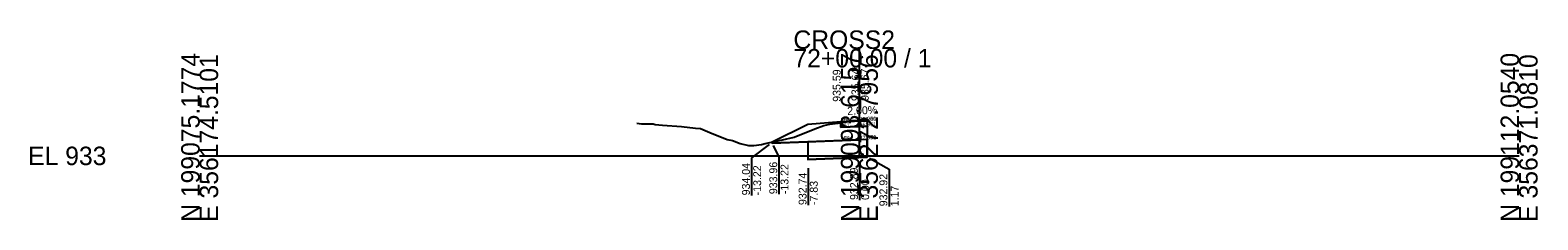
# Model space of a CAD drawing. Extents: x -26 to 203, y -10 to 14021.
# Drawn here: x -25.7 to 202.8, y 12990.3 to 13019.1 of the extents above; entities that cross this region are included whole.
import ezdxf

# ---------------------------------------------------------------- set-up
doc = ezdxf.new("R2010")
doc.units = 0
for name, color, linetype in [('Default', 7, 'Continuous'), ('P_E_XS_Ground', 7, 'Continuous'), ('P_XS', 7, 'Continuous'), ('P_XS_Bold', 7, 'Continuous'), ('P_XS_EAR_CommonGrnd', 7, 'Continuous'), ('P_XS_Lane', 7, 'Continuous'), ('P_XS_Rock', 7, 'Continuous')]:
    doc.layers.add(name, color=color, linetype=linetype)

msp = doc.modelspace()

# ---------------------------------------------------------------- linework, layer by layer
at = {"layer": 'Default'}
for p, q in [((100, 13000), (100, 13016.21)), ((0, 13000), (100, 13000)), ((100, 13000), (200, 13000))]:
    msp.add_line(p, q, dxfattribs=at)
at = {"layer": 'P_E_XS_Ground'}
for p, q in [((66.26, 13004.98), (66.99, 13004.88)), ((66.99, 13004.88), (68.73, 13004.84)), ((68.73, 13004.84), (69.04, 13004.77)), ((69.04, 13004.77), (70.15, 13004.66)), ((70.15, 13004.66), (73.05, 13004.44)), ((73.05, 13004.44), (75.17, 13004.22)), ((75.17, 13004.22), (75.92, 13004.16)), ((75.92, 13004.16), (77.32, 13003.56)), ((77.32, 13003.56), (79.94, 13002.5)), ((90.11, 13002.84), (93.24, 13004.1)), ((93.24, 13004.1), (94.61, 13004.59)), ((94.61, 13004.59), (95.5, 13004.82)), ((95.5, 13004.82), (97.28, 13005.05)), ((97.28, 13005.05), (98.42, 13005.22)), ((98.42, 13005.22), (98.9, 13005.29)), ((98.9, 13005.29), (100, 13005.32)), ((100, 13005.32), (100.66, 13005.34)), ((100.66, 13005.34), (101.18, 13005.4)), ((79.94, 13002.5), (80.76, 13002.31)), ((80.76, 13002.31), (81.92, 13001.86)), ((81.92, 13001.86), (83.21, 13001.58)), ((83.21, 13001.58), (83.99, 13001.55)), ((83.99, 13001.55), (85.16, 13001.74)), ((85.16, 13001.74), (85.71, 13001.86)), ((85.71, 13001.86), (88.35, 13002.41)), ((88.35, 13002.41), (90.11, 13002.84))]:
    msp.add_line(p, q, dxfattribs=at)
at = {"layer": 'P_XS'}
for p, q in [((97.17, 13004.34), (97.17, 13005.17)), ((97.17, 13004.34), (100, 13004.45)), ((101.17, 13004.5), (100, 13004.45)), ((101.17, 13005.33), (101.17, 13004.5)), ((101.17, 13004.5), (101.17, 13002.5)), ((86.78, 13001.92), (100, 13002.45)), ((86.78, 13002.08), (86.78, 13001.92)), ((92.17, 13002.14), (92.17, 12999.47)), ((101.17, 13002.5), (100, 13002.45)), ((101.17, 13002.5), (101.17, 12999.83)), ((101.17, 12999.83), (92.17, 12999.47))]:
    msp.add_line(p, q, dxfattribs=at)
at = {"layer": 'P_XS_EAR_CommonGrnd'}
for points in [[(93.24, 13004.1), (94.61, 13004.59), (95.5, 13004.82), (97.17, 13005.03), (97.17, 13005.17), (92.17, 13004.77), (86.78, 13002.08), (88.35, 13002.41), (90.11, 13002.84)], [(101.17, 13002.5), (100, 13002.45), (92.17, 13002.14), (86.78, 13001.92), (86.78, 13002.08), (88.35, 13002.41), (90.11, 13002.84), (93.24, 13004.1), (94.61, 13004.59), (95.5, 13004.82), (97.17, 13005.03), (97.17, 13004.34), (100, 13004.45), (101.17, 13004.5)], [(97.17, 13005.03), (97.28, 13005.05), (98.42, 13005.22), (98.49, 13005.23), (100, 13005.29), (101.17, 13005.33), (101.17, 13004.5), (100, 13004.45), (97.17, 13004.34)], [(97.17, 13005.03), (97.28, 13005.05), (98.42, 13005.22), (98.49, 13005.23), (97.17, 13005.17)], [(100, 13005.29), (101.17, 13005.33), (101.17, 13005.4), (100.66, 13005.34), (100, 13005.32), (98.9, 13005.29), (98.49, 13005.23)], [(101.17, 13002.5), (100, 13002.45), (92.17, 13002.14), (92.17, 12999.47), (101.17, 12999.83)]]:
    msp.add_lwpolyline(points, close=True, dxfattribs=at)
at = {"layer": 'P_XS_Lane'}
for p, q in [((92.17, 13004.77), (86.78, 13002.08)), ((97.17, 13005.17), (92.17, 13004.77)), ((97.17, 13005.17), (100, 13005.29)), ((100, 13005.29), (101.17, 13005.33)), ((101.17, 13005.33), (101.17, 13005.4))]:
    msp.add_line(p, q, dxfattribs=at)
at = {"layer": 'P_XS_Rock'}
for p, q in [((86.32, 13001.73), (83.66, 12999.71)), ((86.95, 13001.57), (87.8, 12999.82)), ((83.66, 12999.71), (83.66, 12994.02)), ((87.8, 12999.82), (87.8, 12994.2)), ((101.53, 12999.63), (104.49, 12997.97)), ((92.24, 12998.14), (92.24, 12992.55)), ((100.03, 12998.91), (100.03, 12993.31)), ((104.49, 12997.97), (104.49, 12992.35))]:
    msp.add_line(p, q, dxfattribs=at)

# ---------------------------------------------------------------- texts
at = {"layer": 'Default'}
for s, p in [('CROSS2', (90, 13016.21)), ('72+00.00 / 1', (90, 13013.41)), ('EL 933', (-26, 12998.6))]:
    msp.add_text(s, height=2.8, dxfattribs=at).set_placement(p)
for s, p in [('N 199075.1774', (0, 12990)), ('E 356174.5101', (2.8, 12990)), ('N 199093.6157', (100, 12990)), ('E 356272.7956', (102.8, 12990)), ('N 199112.0540', (200, 12990)), ('E 356371.0810', (202.8, 12990))]:
    msp.add_text(s, height=2.8, rotation=90, dxfattribs=at).set_placement(p)
at = {"layer": 'P_XS_Bold'}
for s, p in [('952', (100, 13005.29)), ('952', (100, 13005.29)), ('951', (101.17, 13005.33)), ('9', (101.17, 13005.33)), ('900', (101.17, 13005.33)), ('910', (101.17, 13005.33)), ('951', (97.17, 13005.17)), ('9', (97.17, 13005.17)), ('900', (97.17, 13005.17)), ('961', (97.17, 13004.34)), ('962', (100, 13004.45)), ('962', (100, 13004.45)), ('961', (101.17, 13004.5)), ('971', (97.17, 13002.34)), ('998', (97.17, 13002.34)), ('972', (100, 13002.45)), ('972', (100, 13002.45)), ('971', (101.17, 13002.5)), ('998', (101.17, 13002.5)), ('540', (101.17, 13002.5))]:
    msp.add_text(s, height=0.6, dxfattribs=at).set_placement(p)
at = {"layer": 'P_XS_Rock'}
for s, rotation, p in [('935.59', 90, (97.17, 13008.2)), ('935.64', 90, (100, 13008.31)), ('935.64', 90, (100, 13008.31)), ('935.64', 90, (100, 13008.31)), ('935.64', 90, (100, 13008.31)), ('935.67', 90, (101.42, 13008.34)), ('2.00%', 2.2906, (98.18, 13006.21)), ('933.96', 90, (87.55, 12994.2)), ('934.04', 90, (83.41, 12994.02)), ('-13.22', 90, (85.11, 12994.02)), ('-13.22', 90, (89.25, 12994.2)), ('932.74', 90, (91.99, 12992.55)), ('932.89', 90, (99.78, 12993.32)), ('932.92', 90, (104.24, 12992.36)), ('-7.83', 90, (93.69, 12992.55)), ('0.00', 90, (101.48, 12993.32)), ('1.17', 90, (105.94, 12992.36))]:
    msp.add_text(s, height=1.2, rotation=rotation, dxfattribs=at).set_placement(p)

doc.saveas('drawing.dxf')
